Omron CX-Programmer project NuevoProyecto (CX-Programmer 9.50)

# PLC NewPLC1: CP1L-E EM

## Program P8_1 (cyclic task 0)
Local symbols
CIN1_De 100.04 BOOL
CIN1_Iz 100.03 BOOL
CIN2 100.05 BOOL
D 100.06 BOOL
ELA 100.00 BOOL
ELB 100.01 BOOL
ELC 100.02 BOOL
Etapa_0 10.00 BOOL
Etapa_1 10.01 BOOL
Etapa_10 10.10 BOOL
Etapa_11 10.11 BOOL
Etapa_12 10.12 BOOL
Etapa_13 10.13 BOOL
Etapa_14 10.14 BOOL
Etapa_2 10.02 BOOL
Etapa_3 10.03 BOOL
Etapa_4 10.04 BOOL
Etapa_5 10.05 BOOL
Etapa_6 10.06 BOOL
Etapa_7 10.07 BOOL
Etapa_8 10.08 BOOL
Etapa_9 10.09 BOOL
F1 0.02 BOOL
F2 0.03 BOOL
FSS1 15.00 BOOL  ; Flanco de Subida de S1
S_1 0.01 BOOL
m 0.00 BOOL

### Section Sección1_Programa_principal
; Programa principal (Etapas 0 ... 14)

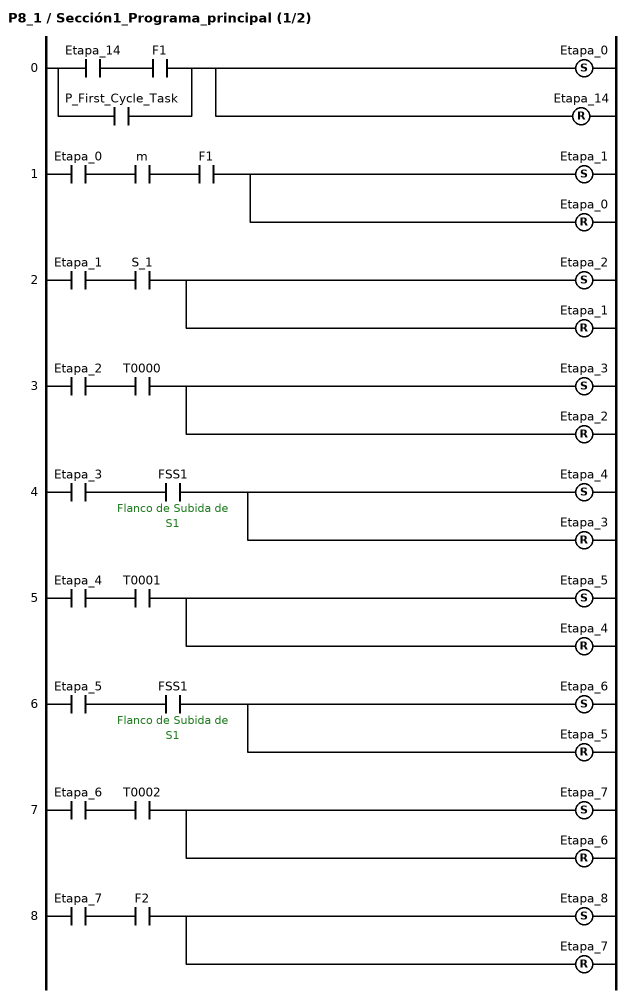
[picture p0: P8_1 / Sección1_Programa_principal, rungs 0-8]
; rung 0
LD Etapa_14
AND F1
OR P_First_Cycle_Task
SET Etapa_0
RSET Etapa_14
; rung 1
LD Etapa_0
AND m
AND F1
SET Etapa_1
RSET Etapa_0
; rung 2
LD Etapa_1
AND S_1
SET Etapa_2
RSET Etapa_1
; rung 3
LD Etapa_2
AND T0000
SET Etapa_3
RSET Etapa_2
; rung 4
LD Etapa_3
AND FSS1  ; Flanco de Subida de S1  // El FSS1 también puede conseguirse mediante variable diferenciada en los autómatas que lo permitan
SET Etapa_4
RSET Etapa_3
; rung 5
LD Etapa_4
AND T0001
SET Etapa_5
RSET Etapa_4
; rung 6
LD Etapa_5
AND FSS1  ; Flanco de Subida de S1
SET Etapa_6
RSET Etapa_5
; rung 7
LD Etapa_6
AND T0002
SET Etapa_7
RSET Etapa_6
; rung 8
LD Etapa_7
AND F2
SET Etapa_8
RSET Etapa_7

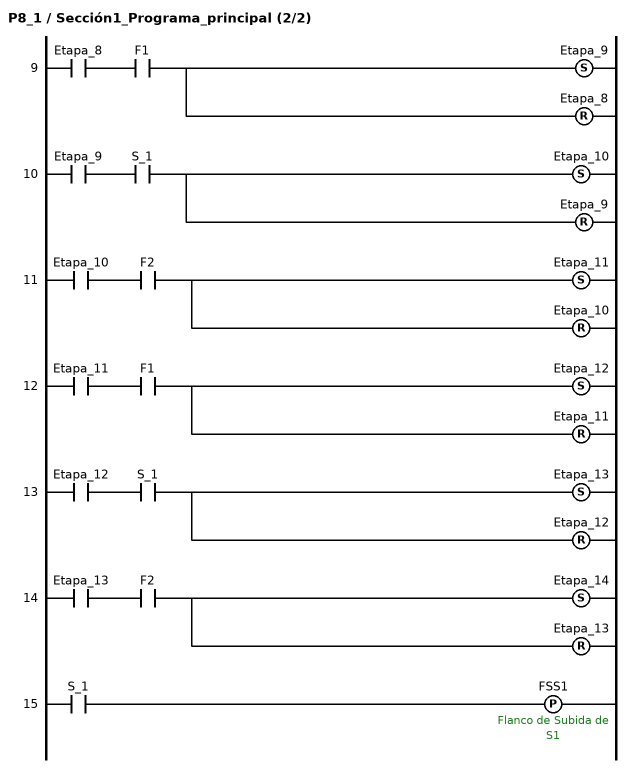
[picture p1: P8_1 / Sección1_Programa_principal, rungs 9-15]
; rung 9
LD Etapa_8
AND F1
SET Etapa_9
RSET Etapa_8
; rung 10
LD Etapa_9
AND S_1
SET Etapa_10
RSET Etapa_9
; rung 11
LD Etapa_10
AND F2
SET Etapa_11
RSET Etapa_10
; rung 12
LD Etapa_11
AND F1
SET Etapa_12
RSET Etapa_11
; rung 13
LD Etapa_12
AND S_1
SET Etapa_13
RSET Etapa_12
; rung 14
LD Etapa_13
AND F2
SET Etapa_14
RSET Etapa_13
; rung 15
LD S_1
DIFU(013) FSS1  ; Flanco de Subida de S1

### Section Sección2_Temporizadores

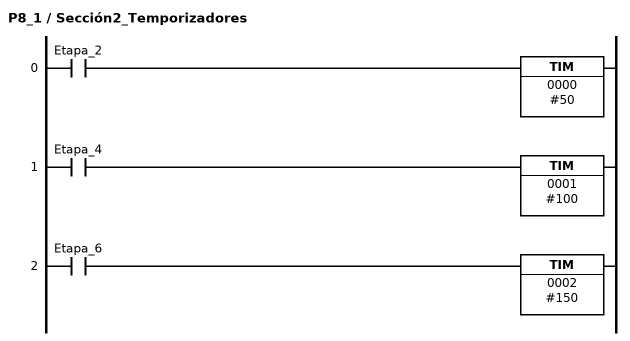
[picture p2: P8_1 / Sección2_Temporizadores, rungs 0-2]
; rung 0
LD Etapa_2
TIM 0000 #50
; rung 1
LD Etapa_4
TIM 0001 #100
; rung 2
LD Etapa_6
TIM 0002 #150

### Section Sección3_Salidas
; Salidas

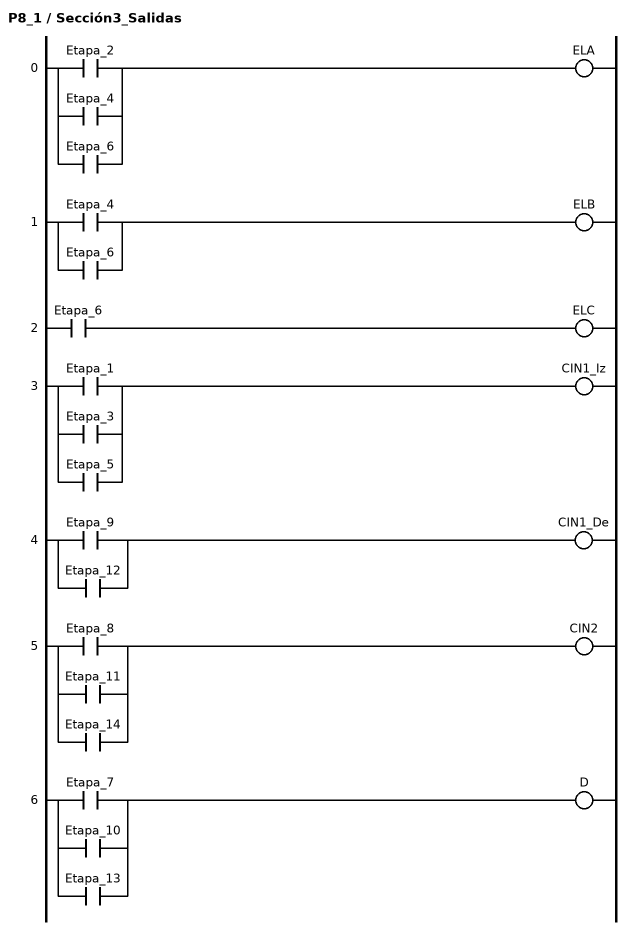
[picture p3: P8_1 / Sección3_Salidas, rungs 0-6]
; rung 0
LD Etapa_2
OR Etapa_4
OR Etapa_6
OUT ELA
; rung 1
LD Etapa_4
OR Etapa_6
OUT ELB
; rung 2
LD Etapa_6
OUT ELC
; rung 3
LD Etapa_1
OR Etapa_3
OR Etapa_5
OUT CIN1_Iz
; rung 4
LD Etapa_9
OR Etapa_12
OUT CIN1_De
; rung 5
LD Etapa_8
OR Etapa_11
OR Etapa_14
OUT CIN2
; rung 6
LD Etapa_7
OR Etapa_10
OR Etapa_13
OUT D

### Section Sección4_END
; rung 0
END(001)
